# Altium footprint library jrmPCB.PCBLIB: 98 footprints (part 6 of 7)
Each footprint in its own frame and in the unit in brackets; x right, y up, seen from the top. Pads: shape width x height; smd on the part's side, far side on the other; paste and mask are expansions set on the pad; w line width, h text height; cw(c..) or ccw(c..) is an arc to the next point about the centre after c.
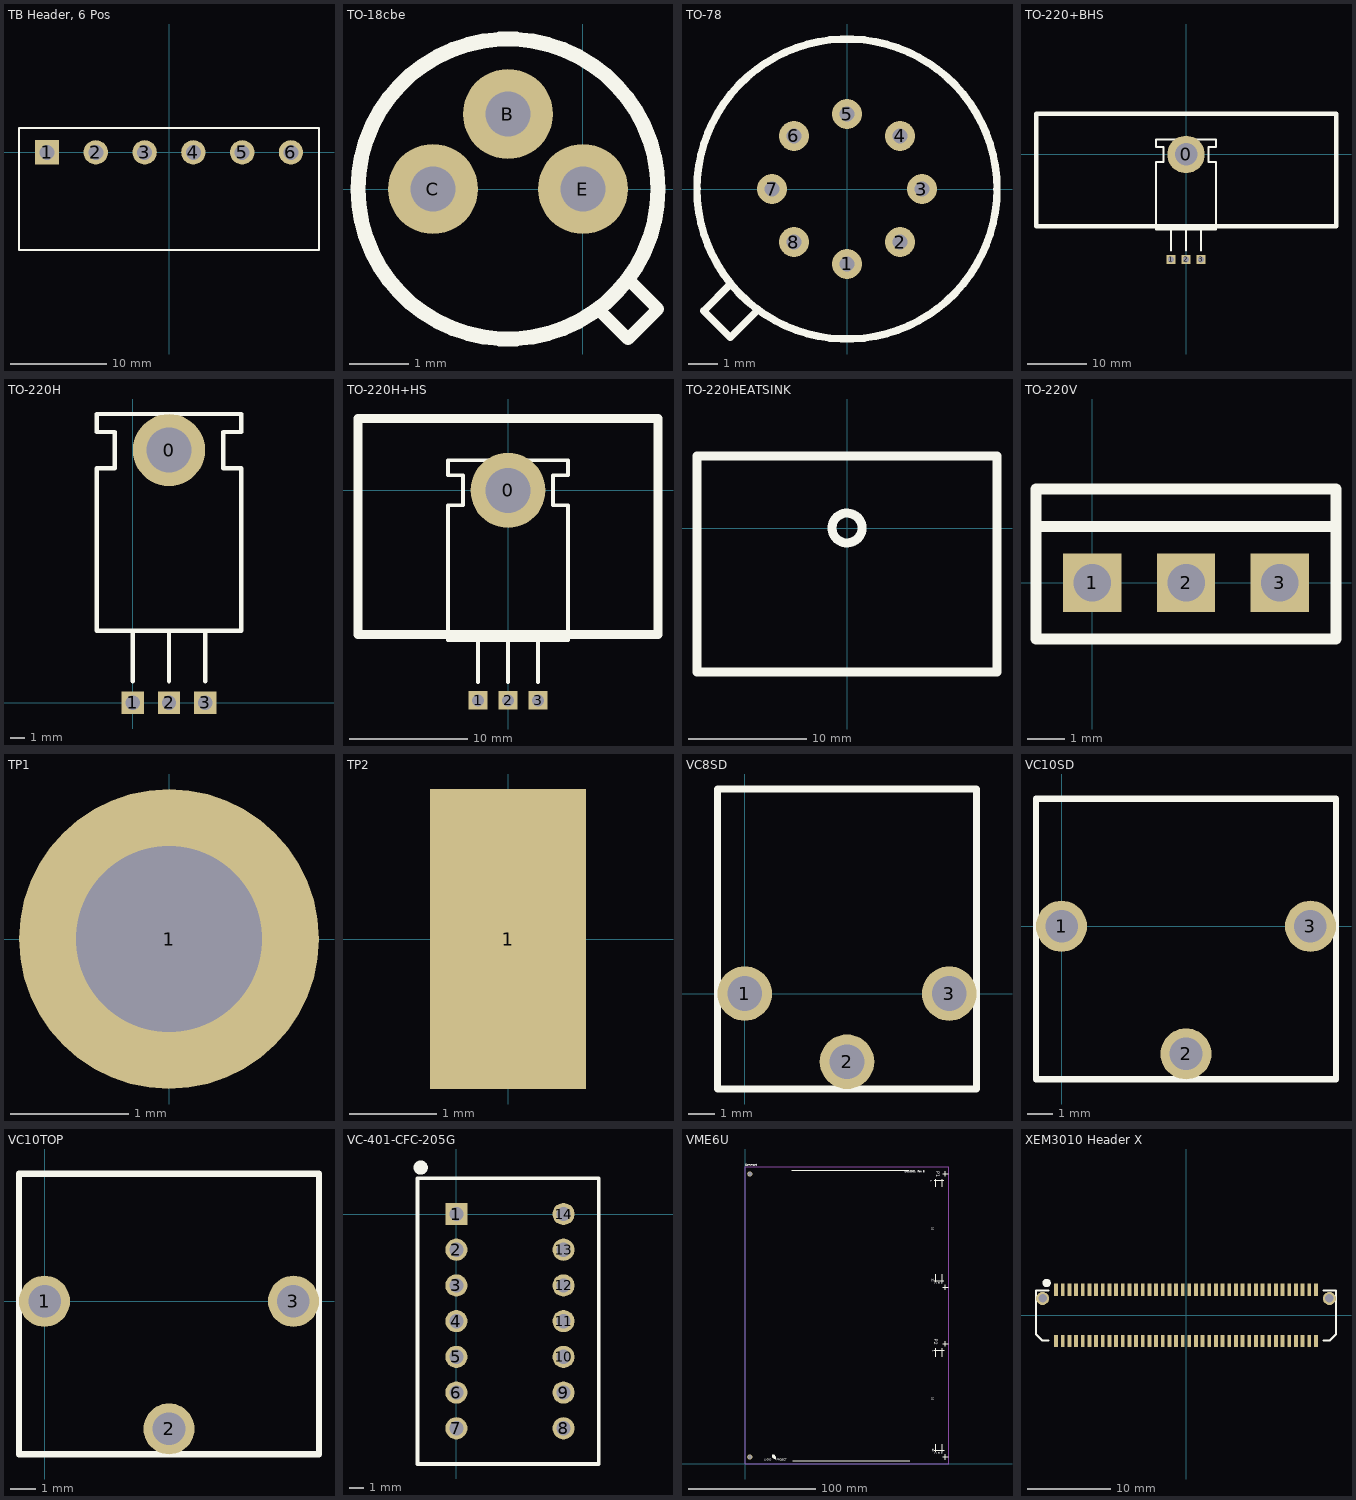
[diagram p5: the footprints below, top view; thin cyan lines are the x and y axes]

## TB Header, 6 Pos [mil]
pads (6):
  rect 100x100 hole 62: 1(-500,0)
  round 100 hole 62: 2(-300,0) 3(-100,0) 4(100,0) 5(300,0) 6(500,0)
Top Overlay:
  lines w10: -615,-400 615,-400 615,100 -615,100 -615,-400

## TO-18cbe [mil]
pads (3):
  round 60 hole 30: B(-50,50) C(-100,0) E(0,0)
Top Overlay:
  circle w10: c-50,0 r100
  lines w8: 10,-80 30,-100 50,-80 30,-60

## TO-78 [mil]
pads (8):
  round 40 hole 20: 1(0,-100) 2(70.71,-70.71) 3(100,0) 4(70.71,70.71) 5(0,100) 6(-70.71,70.71) 7(-100,0) 8(-70.71,-70.71)
Top Overlay:
  circle w10: c0,0 r200
  lines w10: -155.56,-127.28 -190.92,-162.63 -155.56,-197.99 -120.21,-162.63

## TO-220+BHS [mil]
pads (4):
  round 250 hole 150: 0(0,0)
  rect 62x62 hole 40: 1(-100,-700) 2(0,-700) 3(100,-700)
Top Overlay:
  circle w30: c0,0 r50
  lines w12: -100,-640 -100,-500 ; 0,-640 0,-500 ; 100,-640 100,-500 ; -200,-500 200,-500 200,-50 150,-50 150,50 200,50 200,100 -200,100 -200,50 -150,50 -150,-50 -200,-50 -200,-500
  lines w30: 480,-480 1000,-480 ; 1000,-480 1000,270 -1000,270 -1000,-480 1000,-480

## TO-220H [mil]
pads (4):
  round 200 hole 125: 0(100,700)
  rect 62x62 hole 40: 1(0,0) 2(100,0) 3(200,0)
Top Overlay:
  lines w12: 0,60 0,200 ; 100,60 100,200 ; 200,60 200,200 ; -100,200 300,200 300,650 250,650 250,750 300,750 300,800 -100,800 -100,750 -50,750 -50,650 -100,650 -100,200

## TO-220H+HS [mil] "TO220 Package with surround for heatsink"
height 750
pads (4):
  round 250 hole 150: 0(0,0)
  rect 62x62 hole 40: 1(-100,-700) 2(0,-700) 3(100,-700)
Top Overlay:
  circle w30: c0,0 r50
  lines w12: -100,-640 -100,-500 ; 0,-640 0,-500 ; 100,-640 100,-500 ; -200,-500 200,-500 200,-50 150,-50 150,50 200,50 200,100 -200,100 -200,50 -150,50 -150,-50 -200,-50 -200,-500
  lines w30: 480,-480 500,-480 ; 500,-480 500,240 -500,240 -500,-480 500,-480

## TO-220HEATSINK [mil]
Top Overlay:
  circle w30: c0,0 r50
  lines w30: 480,-480 500,-480 ; 500,-480 500,240 -500,240 -500,-480 500,-480

## TO-220V [mil]
pads (3):
  rect 62x62 hole 40: 1(0,0) 2(100,0) 3(200,0)
Top Overlay:
  lines w12: -60,60 -60,100 260,100 260,60 ; -60,60 260,60 ; -60,60 -60,-60 260,-60 260,60

## TP1 [mil]
pads (1):
  round 100 hole 62: 1(0,0)

## TP2 [mil]
pads (1):
  rect 70x135 smd: 1(0,0)

## VC8SD [mil]
pads (3):
  round 80 hole 51: 1(0,0) 2(150,-100) 3(300,0)
Top Overlay:
  lines w10: -40,-140 -40,300 0,300 300,300 340,300 340,-140 300,-140 0,-140 -40,-140

## VC10SD [mil]
pads (3):
  round 80 hole 51: 1(0,0) 2(195,-200) 3(390,0)
Top Overlay:
  lines w10: -40,-240 -40,200 30,200 330,200 430,200 430,-240 300,-240 0,-240 -40,-240

## VC10TOP [mil]
pads (3):
  round 80 hole 51: 1(0,0) 2(195,-200) 3(390,0)
Top Overlay:
  lines w10: -40,-240 0,-240 300,-240 430,-240 430,200 330,200 30,200 -40,200 -40,-240

## VC-401-CFC-205G [mil]
pads (14):
  rect 62x62 hole 40: 1(0,0)
  round 62 hole 40: 2(0,-100) 3(0,-200) 4(0,-300) 5(0,-400) 6(0,-500) 7(0,-600) 8(300,-600) 9(300,-500) 10(300,-400) 11(300,-300) 12(300,-200) 13(300,-100) 14(300,0)
Top Overlay:
  circle w20: c-100,130 r10
  lines w10: -109,40 -109,41 ; -109,-700 -109,100 399,100 399,-700 -109,-700

## VME6U [mil]
pads (2):
  round 160 hole 120: 0(136.75,214.53) 0(137.73,8965.52)
Top Overlay:
  lines w9.84: 824,284 ccw(c944,284) 944,164 ; 844,284 ccw(c944,284) 944,184 ; 864,284 ccw(c944,284) 944,204 ; 884,284 ccw(c944,284) 944,224 ; 1429,9084 5057,9084 ; 1470,96 5086,96 ; 5845,415 6145,415 ; 5845,3515 6145,3515 ; 5846,5666 6126,5666 ; 5846,8766 5886,8766 ; 5885,375 5885,615 ; 5885,3315 5885,3575 ; 5886,5626 5886,5866 ; 5886,8566 5886,8766 ; 5886,8806 5886,8766 ; 6085,375 6085,615 ; 6085,3315 6085,3575 ; 6086,5626 6086,5866 ; 6086,8566 6086,8766 ; 6086,8806 6086,8766 ; 6105,215 6265,215 ; 6105,3715 6265,3715 ; 6105,8965 6265,8965 ; 6106,5466 6266,5466 ; 6126,8766 6086,8766 ; 6185,135 6185,295 ; 6185,3635 6185,3795 ; 6186,5386 6186,5546 ; 6186,8886 6186,9046 ; 5886,8766 6086,8766
  text "Comment" at -9.9,9206.98 h60
  text "D010001, Rev B" at 4920,9005 h60
  text "P2" at 5842,3863 h110
  text "A" at 6060,5616 h60
  text "B" at 5961,5615 h60
  text "C" at 5851,5613 h60
  text "32" at 5756,5718 h60
  text "1" at 5712,8776 h60
  text "16" at 5766,2055 h60
  text "1" at 5771,3521 h60
  text "32" at 5771,465 h60
  text "A" at 6059,357 h60
  text "B" at 5956,353 h60
  text "C" at 5857,354 h60
  text "LIGO" at 584,104 h72
  text "PROJECT" at 964,104 h60
  text "16" at 5769,7310 h60
  text "P1" at 5896,9055 h110
  text "Comment" at -6.65,9212.44 h60
  text "D010001, Rev B" at 4923.25,9010.47 h60
Mechanical 1:
  lines w9.84: 6014.7,9182.06 6294.23,9182.06 6294.23,8784.42 ; 6018.64,9182.06 -4.98,9182.06 -4.98,-2.98 6294.23,-2.98 6294.23,8788.35

## XEM3010 Header X [mm]
pads (82):
  rect 0.46x1.45 smd: X1(-15.6,3.085) X2(-15.6,-3.085) X3(-14.8,3.085) X4(-14.8,-3.085) X5(-14,3.085) X6(-14,-3.085) X7(-13.2,3.085) X8(-13.2,-3.085) X9(-12.4,3.085) X10(-12.4,-3.085) X11(-11.6,3.085) X12(-11.6,-3.085) X13(-10.8,3.085) X14(-10.8,-3.085) X15(-10,3.085) X16(-10,-3.085) X17(-9.2,3.085) X18(-9.2,-3.085) X19(-8.4,3.085) X20(-8.4,-3.085) X21(-7.6,3.085) X22(-7.6,-3.085) X23(-6.8,3.085) X24(-6.8,-3.085) X25(-6,3.085) X26(-6,-3.085) X27(-5.2,3.085) X28(-5.2,-3.085) X29(-4.4,3.085) X30(-4.4,-3.085) X31(-3.6,3.085) X32(-3.6,-3.085) X33(-2.8,3.085) X34(-2.8,-3.085) X35(-2,3.085) X36(-2,-3.085) X37(-1.2,3.085) X38(-1.2,-3.085) X39(-0.4,3.085) X40(-0.4,-3.085) X41(0.4,3.085) X42(0.4,-3.085) X43(1.2,3.085) X44(1.2,-3.085) X45(2,3.085) X46(2,-3.085) X47(2.8,3.085) X48(2.8,-3.085) X49(3.6,3.085) X50(3.6,-3.085) X51(4.4,3.085) X52(4.4,-3.085) X53(5.2,3.085) X54(5.2,-3.085) X55(6,3.085) X56(6,-3.085) X57(6.8,3.085) X58(6.8,-3.085) X59(7.6,3.085) X60(7.6,-3.085) X61(8.4,3.085) X62(8.4,-3.085) X63(9.2,3.085) X64(9.2,-3.085) X65(10,3.085) X66(10,-3.085) X67(10.8,3.085) X68(10.8,-3.085) X69(11.6,3.085) X70(11.6,-3.085) X71(12.4,3.085) X72(12.4,-3.085) X73(13.2,3.085) X74(13.2,-3.085) X75(14,3.085) X76(14,-3.085) X77(14.8,3.085) X78(14.8,-3.085) X79(15.6,3.085) X80(15.6,-3.085)
  round 1.575 hole 1.016: X81(-17.235,2.035) X82(17.235,2.035)
Top Overlay:
  circle w0.5: c-16.75,3.9 r0.25
  lines w0.254: -16.5,-3 -17.3,-3 -18,-2.3 -18,3 -16.5,3 ; 16.5,-3 17.3,-3 18,-2.3 18,3 16.5,3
